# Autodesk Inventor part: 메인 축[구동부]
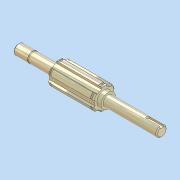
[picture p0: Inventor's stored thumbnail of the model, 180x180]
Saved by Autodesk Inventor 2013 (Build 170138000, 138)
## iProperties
Company: 한국ATC센터
Created: 2012-05
Part Number: 메인 축[구동부]
Document SubType Name: 모델링
Designer: KYOUNG IL JANG
Mass: 168.566 g
Surface Area: 72.5108 cm^2
Volume: 21.4461 cm^3
Density: 7.86 g/cm^3
Material: 강, 연강
변환 표준: STEP AP214IS
파일 이름: C:\Users\SeoGD\Desktop\?쒗뿕\硫붿씤 異?.stp
전처리기: Build: 253, Release: 2010 SP1 - Date: Wed 07/29/2009
전송 단위: 밀리미터
불확실성: 0.01
Author: KYOUNG IL JANG
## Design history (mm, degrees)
sketch "스케치1"
  geometry: L1 (-69.5, 0)-(69.5, 0); L2 (69.5, 0)-(69.5, 5); L3 (69.5, 5)-(55.5, 5); L4 (55.5, 5)-(55.5, 4.8); L5 (55.5, 4.8)-(54.35, 4.8); L6 (54.35, 4.8)-(54.35, 5); L7 (54.35, 5)-(30.5, 5); L8 (30.5, 5)-(30.5, 9); L9 (30.5, 9)-(-13.5, 9); L10 (-13.5, 9)-(-13.5, 7); L11 (-13.5, 7)-(-17.5, 7); L12 (-17.5, 7)-(-17.5, 5); L13 (-17.5, 5)-(-69.5, 5); L14 (-69.5, 5)-(-69.5, 0); 2 further points
  constraints: 28 end point, 9 parallel, 4 collinear, 2 perpendicular, 1 coincident, 1 horizontal, 1 midpoint
  dimensions: "d2" = 1.15 distance between parallel lines of L6 L4; "d3" = 10 diameter of L3 L1; "d4" = 9.6 diameter of L5 L1; "d6" = 44 distance between parallel lines of L10 L8; "d7" = 4 distance between parallel lines of L12 L10; "d8" = 14 diameter of L11 L1; "d9" = 18 diameter of L9 L1; "d33" = 52 distance from line of L12.end L14; "d37" = 39 distance between parallel lines of L8 L2; "d38" = 14 distance between parallel lines of L2 L4
revolve "회전1" sketch "스케치1" stored, may be unused: angle "d10" = 90 deg
sketch "스케치2"
  geometry: L1 (2.5, 10.712)-(2.5, 8.646); L2 (-2.5, 10.712)-(-2.5, 8.646); A1 r 9 centre (0, 0) between (2.5, 8.646) and (-2.5, 8.646) reference; A2 r 11 centre (0, 0) between (2.5, 10.712) and (-2.5, 10.712); 1 further point
  constraints: 4 end point, 4 point on circle, 2 parallel, 1 centre point, 1 coincident, 1 vertical
  dimensions: "d11" = 22 diameter of A2; "d12" = 5 distance between parallel lines of L1 L2
extrude "돌출1" join sketch "스케치2" stored distance "d13" = 10; taper "d14" = 0 deg
chamfer "모따기1" distance "d15" = 1; stored, may be unused: second distance "d16" = 2, angle "d17" = 45 deg
node "작업 평면1"
node "작업 평면2"
sketch "스케치3"
  geometry: L1 (2.5, 10.712)-(2.5, 10.198); L2 (-2.5, 10.712)-(-2.5, 10.198); A1 r 11 centre (0, 0) between (2.5, 10.712) and (-2.5, 10.712) reference; A2 r 10.5 centre (0, 0) between (2.5, 10.198) and (-2.5, 10.198); 1 further point
  constraints: 4 end point, 2 point on circle, 1 centre point, 1 coincident, 1 parallel, 1 vertical
  dimensions: "d19" = 21 diameter of A2
extrude "돌출2" cut sketch "스케치3" distance "d20" = 1.35; taper "d21" = 0 deg
node "작업 평면3"
sketch "스케치4"
  geometry: L1 (-26, -5)-(-26, 5) reference; L2 (-26, 1.5)-(-12.5, 1.5); L3 (-12.5, -1.5)-(-26, -1.5); A1 r 1.5 centre (-12.5, 0) between (-12.5, -1.5) and (-12.5, 1.5); 2 further points
  constraints: 4 end point, 2 perpendicular, 2 point on circle, 2 point on line, 2 tangent, 1 centre point, 1 horizontal alignment, 1 midpoint
  dimensions: "d25" = 3 distance between parallel lines of L3 L2; "d26" = 15 dimension on A1 L1
extrude "돌출3" cut sketch "스케치4" distance "d27" = 1.8; taper "d28" = 0 deg
chamfer "모따기2" distance "d29" = 1; stored, may be unused: second distance "d30" = 2, angle "d31" = 45 deg
node "솔리드1"
node "솔리드 본체"
node "곡면 본체"
mirror "대칭1"
pattern_circular "원형 패턴1" dims "d23" = 360 deg
node "솔리드2"
other parameters: "d18" = -1.65
